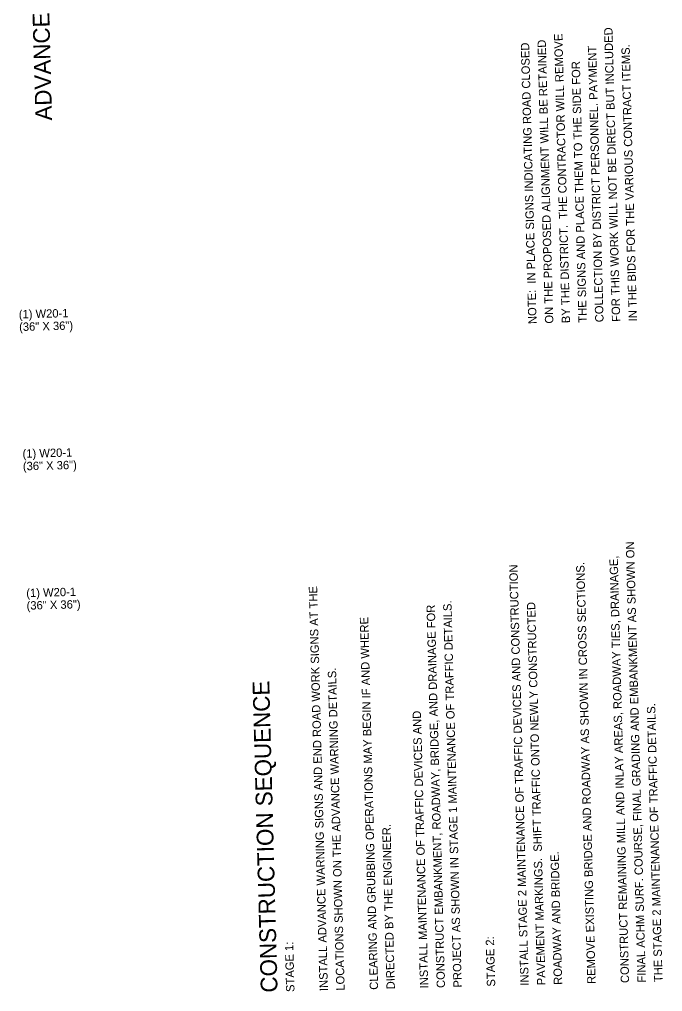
# Model space of a CAD drawing. Extents: x 1930579 to 1931593, y 596452 to 598537.
# Drawn here: x 1931090 to 1931551, y 597129 to 597827 of the extents above; entities that cross this region are included whole.
import ezdxf

# ---------------------------------------------------------------- set-up
doc = ezdxf.new("R2010")
doc.units = 0
doc.layers.add('R_Annotation', color=7, linetype='Continuous')

msp = doc.modelspace()

# ---------------------------------------------------------------- texts
at = {"layer": 'R_Annotation'}
for s, height, rotation, p in [('ADVANCE WARNING DETAILS', 12, 91.53769, (1931113.75, 597754.09)), ('FOR THIS WORK WILL NOT BE DIRECT BUT INCLUDED', 6, 91.53769, (1931521.09, 597609.73)), ('NOTE:  IN PLACE SIGNS INDICATING ROAD CLOSED', 6, 91.53769, (1931461.11, 597608.12)), ('ON THE PROPOSED ALIGNMENT WILL BE RETAINED ', 6, 91.53769, (1931473.11, 597608.44)), ('BY THE DISTRICT.  THE CONTRACTOR WILL REMOVE', 6, 91.53769, (1931485.1, 597608.76)), ('COLLECTION BY DISTRICT PERSONNEL. PAYMENT ', 6, 91.53769, (1931509.09, 597609.4)), ('IN THE BIDS FOR THE VARIOUS CONTRACT ITEMS.', 6, 91.53769, (1931533.08, 597610.05)), ('THE SIGNS AND PLACE THEM TO THE SIDE FOR', 6, 91.53769, (1931497.1, 597609.08)), ('(1) W20-1', 6, 1.53769, (1931089.89, 597612.03)), ('(36" X 36")', 6, 1.53769, (1931090.13, 597603.03)), ('(1) W20-1', 6, 1.53769, (1931092.58, 597512.06)), ('(36" X 36")', 6, 1.53769, (1931092.82, 597503.07)), ('FINAL ACHM SURF. COURSE, FINAL GRADING AND EMBANKMENT AS SHOWN ON', 6, 91.53769, (1931539.41, 597135.72)), ('CONSTRUCT REMAINING MILL AND INLAY AREAS, ROADWAY TIES, DRAINAGE, ', 6, 91.53769, (1931527.41, 597135.4)), ('INSTALL STAGE 2 MAINTENANCE OF TRAFFIC DEVICES AND CONSTRUCTION ', 6, 91.53769, (1931455.44, 597133.47)), ('REMOVE EXISTING BRIDGE AND ROADWAY AS SHOWN IN CROSS SECTIONS.', 6, 91.53769, (1931503.42, 597134.75)), ('(1) W20-1', 6, 1.53769, (1931095.26, 597412.1)), ('INSTALL ADVANCE WARNING SIGNS AND END ROAD WORK SIGNS AT THE', 6, 91.53769, (1931311.49, 597129.6)), ('(36" X 36")', 6, 1.53769, (1931095.5, 597403.1)), ('CONSTRUCT EMBANKMENT, ROADWAY, BRIDGE, AND DRAINAGE FOR', 6, 91.53769, (1931395.46, 597131.86)), ('PROJECT AS SHOWN IN STAGE 1 MAINTENANCE OF TRAFFIC DETAILS. ', 6, 91.53769, (1931407.45, 597132.18)), ('PAVEMENT MARKINGS.  SHIFT TRAFFIC ONTO NEWLY CONSTRUCTED ', 6, 91.53769, (1931467.43, 597133.79)), ('CLEARING AND GRUBBING OPERATIONS MAY BEGIN IF AND WHERE', 6, 91.53769, (1931347.47, 597130.57)), ('LOCATIONS SHOWN ON THE ADVANCE WARNING DETAILS.  ', 6, 91.53769, (1931323.48, 597129.92)), ('CONSTRUCTION SEQUENCE', 12, 91.53769, (1931275.38, 597128.63)), ('THE STAGE 2 MAINTENANCE OF TRAFFIC DETAILS.', 6, 91.53769, (1931551.4, 597136.04)), ('INSTALL MAINTENANCE OF TRAFFIC DEVICES AND ', 6, 91.53769, (1931383.46, 597131.53)), ('DIRECTED BY THE ENGINEER.', 6, 91.53769, (1931359.47, 597130.89)), ('ROADWAY AND BRIDGE.', 6, 91.53769, (1931479.43, 597134.11)), ('STAGE 2:', 6, 91.53769, (1931431.44, 597132.82)), ('STAGE 1:', 6, 91.53769, (1931287.5, 597128.96))]:
    msp.add_text(s, height=height, rotation=rotation, dxfattribs=at).set_placement(p)

doc.saveas('drawing.dxf')
